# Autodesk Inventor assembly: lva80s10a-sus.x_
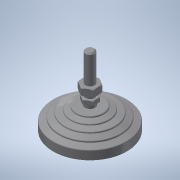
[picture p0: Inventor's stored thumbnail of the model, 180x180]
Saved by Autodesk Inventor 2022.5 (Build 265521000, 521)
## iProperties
Part Number: lva80s10a-sus.x_
Material: 一般
Document SubType Name: Assembly
Designer: ImaoCorp
Sending System: SOLIDWORKS 2017-2017317
MC: AMD64
MC_MODEL: Intel64 Family 6 Model 60 Stepping 3, GenuineIntel
OS: Windows_NT
FRU: Parasolid Version 29.0, build 201,  4-17-2017
FORMAT: text
GUISE: transmit
KEY: lva80s10a-sus
FILE: lva80s10a-sus.x_t
DATE: Mon Jul 01 18:09:24 2019
Author: ImaoCorp
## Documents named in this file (3)
- X:\14_SW2022-Inv2022\00_全2023-1023新製品(TCC)まで\l\lva80s10a-sus\LVA80S10A-SUS.iam
- X:\14_SW2022-Inv2022\00_全2023-1023新製品(TCC)まで\l\lva80s10a-sus\lva80s10a-sus_01.ipt
- X:\14_SW2022-Inv2022\00_全2023-1023新製品(TCC)まで\l\lva80s10a-sus\lva80s10a-sus_02.ipt
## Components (2 placed, 2 different names)
1. lva80s10a-sus_01
2. lva80s10a-sus_02
